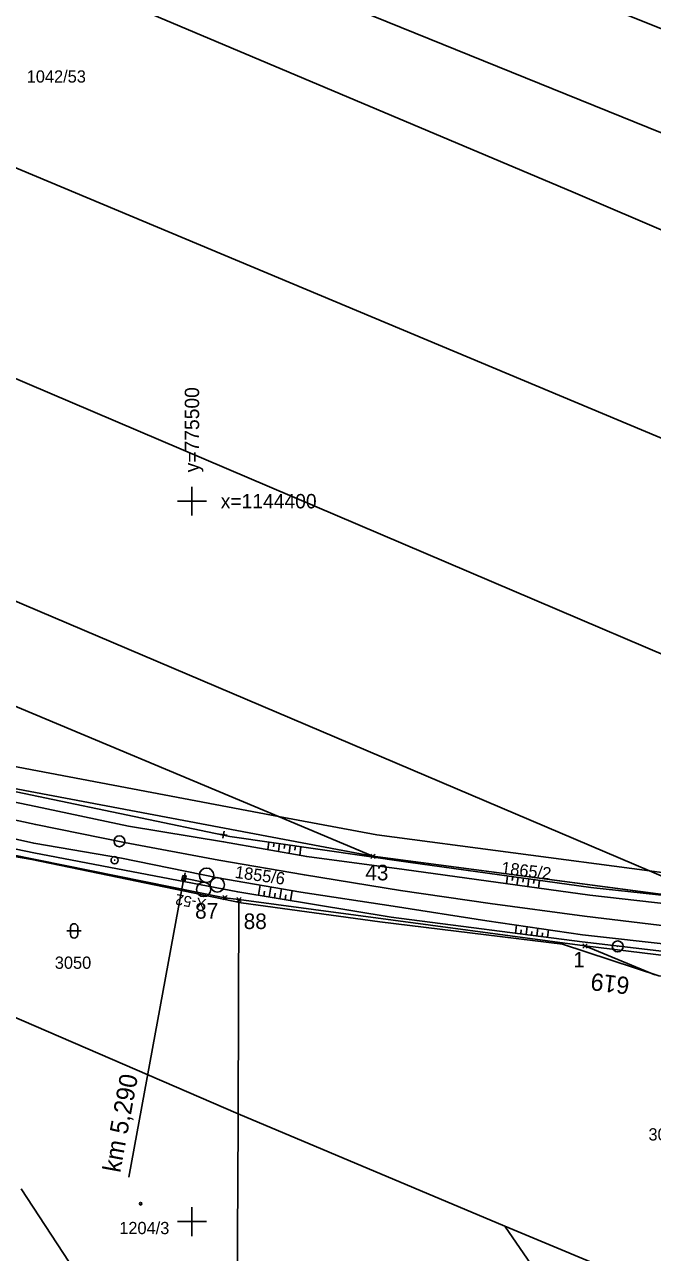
# Model space of a CAD drawing. Extents: x -779302 to -774398, y -1144902 to -1142831.
# Drawn here: x -775523.2 to -775436.1, y -1144504.3 to -1144333.8 of the extents above; entities that cross this region are included whole.
import ezdxf

# ---------------------------------------------------------------- set-up
doc = ezdxf.new("R2010")
doc.units = 0
for name, color, linetype in [('hektosit - Vrstva 5', 7, 'Continuous'), ('Hranice parcel', 7, 'Continuous'), ('legenda I_5_2 - Vrstva 53', 7, 'Continuous'), ('Parcelní čísla', 7, 'Continuous'), ('SŽDC', 7, 'Continuous'), ('zjednodus_g_situ-seda - Vrstva 1', 7, 'Continuous'), ('zjednodus_g_situ-seda - Vrstva 12', 7, 'Continuous'), ('zjednodus_g_situ-seda - Vrstva 17', 7, 'Continuous'), ('zjednodus_g_situ-seda - Vrstva 48', 7, 'Continuous'), ('zjednodus_g_situ-seda - Vrstva 49', 7, 'Continuous'), ('zjednodus_g_situ-seda - Vrstva 63', 7, 'Continuous'), ('zjednodus_g_situ-seda - Vrstva 7', 7, 'Continuous'), ('zjednodus_g_situ-seda - Vrstva 8', 7, 'Continuous'), ('Značky budov', 7, 'Continuous'), ('Značky kultur', 7, 'Continuous')]:
    doc.layers.add(name, color=color, linetype=linetype)

msp = doc.modelspace()

# ---------------------------------------------------------------- linework, layer by layer
at = {"layer": 'hektosit - Vrstva 5'}
for p, q in [((-775500, -1144398), (-775500, -1144402)), ((-775502, -1144400), (-775498, -1144400)), ((-775500, -1144498), (-775500, -1144502)), ((-775502, -1144500), (-775498, -1144500))]:
    msp.add_line(p, q, dxfattribs=at)
at = {"layer": 'Hranice parcel'}
for p, q in [((-775535.75, -1144423.8), (-775487.96, -1144443.76)), ((-775474.88, -1144449.28), (-775487.96, -1144443.76)), ((-775426.17, -1144455.72), (-775474.88, -1144449.28)), ((-775426.17, -1144455.72), (-775436.47, -1144451.33)), ((-775493.58, -1144485.06), (-775493.48, -1144455.3)), ((-775493.48, -1144455.3), (-775445.43, -1144461.73)), ((-775445.43, -1144461.73), (-775435.74, -1144465.74)), ((-775493.58, -1144485.06), (-775539.58, -1144465.16)), ((-775456.54, -1144500.61), (-775493.58, -1144485.06)), ((-775523.71, -1144495.46), (-775507.21, -1144520.6)), ((-775393.05, -1144527.1), (-775456.54, -1144500.61)), ((-775456.54, -1144500.61), (-775385.01, -1144604.68))]:
    msp.add_line(p, q, dxfattribs=at)
for points in [[(-775607.93, -1144251.93), (-775592.73, -1144265.24), (-775577.44, -1144273.94), (-775563.67, -1144281.5), (-775543.76, -1144290.79), (-775411.19, -1144343.87), (-775388.13, -1144354.18)], [(-775632.59, -1144258.06), (-775621.58, -1144265.67), (-775577.27, -1144289.87), (-775522.49, -1144313.33), (-775419.42, -1144355.11), (-775391.09, -1144367.64), (-775389.67, -1144368.26)], [(-775657.22, -1144264.36), (-775641.76, -1144273.65), (-775618.95, -1144284.54), (-775447.05, -1144357.1), (-775391.08, -1144381.09)], [(-775394.06, -1144408.34), (-775619.55, -1144313.89), (-775660.82, -1144292.56), (-775671.23, -1144286.27), (-775688.22, -1144274.1)], [(-775397.11, -1144437.29), (-775575.13, -1144361.42), (-775643.03, -1144333.5), (-775681.69, -1144314.82), (-775705.2, -1144302.37), (-775726.91, -1144287.21)], [(-775773.94, -1144303.16), (-775745.45, -1144320.86), (-775720.13, -1144333.58), (-775665.78, -1144356.01), (-775632.16, -1144368.38), (-775595.92, -1144383.54), (-775436.47, -1144451.33)], [(-775474.88, -1144449.28), (-775529.11, -1144439.07), (-775574.03, -1144428.55), (-775626.91, -1144413.11), (-775690.5, -1144389.48), (-775838.53, -1144328.62), (-775848.16, -1144325.04)], [(-775539.06, -1144434.24), (-775528.56, -1144436.11), (-775487.96, -1144443.76)], [(-775487.96, -1144443.76), (-775474.32, -1144446.33), (-775436.47, -1144451.33)], [(-775532.74, -1144447.53), (-775495.43, -1144455.04), (-775493.48, -1144455.3)], [(-775436.47, -1144451.33), (-775417.75, -1144453.81), (-775384.8, -1144455.7)], [(-775389.68, -1144468.46), (-775425.39, -1144464.15), (-775445.43, -1144461.73)], [(-775489.41, -1144542.39), (-775493.92, -1144534.76), (-775493.7, -1144510.05), (-775493.58, -1144486.33), (-775493.58, -1144485.06)]]:
    msp.add_lwpolyline(points, dxfattribs=at)
at = {"layer": 'legenda I_5_2 - Vrstva 53'}
for points in [[(-776052.08, -1144238.11), (-776022.68, -1144250.27), (-776023.78, -1144252.86), (-775962.18, -1144277.9), (-775959.79, -1144278.81), (-775958.42, -1144279.33), (-775955.63, -1144280.49), (-775876.16, -1144313.52), (-775863.23, -1144318.85), (-775854.19, -1144322.57), (-775848.16, -1144325.04), (-775838.53, -1144328.62), (-775690.5, -1144389.48), (-775626.91, -1144413.11), (-775574.03, -1144428.55), (-775529.11, -1144439.07), (-775474.88, -1144449.28), (-775426.17, -1144455.72)], [(-775425.39, -1144464.15), (-775445.43, -1144461.73), (-775493.48, -1144455.3), (-775495.43, -1144455.04), (-775532.74, -1144447.53), (-775560.62, -1144440.02), (-775576.16, -1144435.84), (-775611.43, -1144425.73), (-775655.04, -1144411.89), (-775699.86, -1144394.42)]]:
    msp.add_lwpolyline(points, dxfattribs=at)
at = {"layer": 'SŽDC'}
for p, q in [((-775474.68, -1144449.48), (-775475.18, -1144448.98)), ((-775474.68, -1144449.08), (-775475.18, -1144449.58)), ((-775475.08, -1144449.48), (-775474.58, -1144448.98)), ((-775475.08, -1144449.08), (-775474.58, -1144449.58)), ((-775474.88, -1144449.28), (-775474.88, -1144449.28)), ((-775495.23, -1144455.24), (-775495.73, -1144454.74)), ((-775495.23, -1144454.84), (-775495.73, -1144455.34)), ((-775495.63, -1144455.24), (-775495.13, -1144454.74)), ((-775495.63, -1144454.84), (-775495.13, -1144455.34)), ((-775495.43, -1144455.04), (-775495.43, -1144455.04)), ((-775493.28, -1144455.5), (-775493.78, -1144455)), ((-775493.28, -1144455.1), (-775493.78, -1144455.6)), ((-775493.68, -1144455.5), (-775493.18, -1144455)), ((-775493.68, -1144455.1), (-775493.18, -1144455.6)), ((-775493.48, -1144455.3), (-775493.48, -1144455.3)), ((-775445.23, -1144461.93), (-775445.73, -1144461.43)), ((-775445.23, -1144461.53), (-775445.73, -1144462.03)), ((-775445.63, -1144461.93), (-775445.13, -1144461.43)), ((-775445.63, -1144461.53), (-775445.13, -1144462.03)), ((-775445.43, -1144461.73), (-775445.43, -1144461.73))]:
    msp.add_line(p, q, dxfattribs=at)
for points in [[(-776052.08, -1144238.11), (-776022.68, -1144250.27), (-776023.78, -1144252.86), (-775962.18, -1144277.9), (-775959.79, -1144278.81), (-775958.42, -1144279.33), (-775955.63, -1144280.49), (-775876.16, -1144313.52), (-775863.23, -1144318.85), (-775854.19, -1144322.57), (-775848.16, -1144325.04), (-775838.53, -1144328.62), (-775690.5, -1144389.48), (-775626.91, -1144413.11), (-775574.03, -1144428.55), (-775529.11, -1144439.07), (-775474.88, -1144449.28), (-775426.17, -1144455.72)], [(-775425.39, -1144464.15), (-775445.43, -1144461.73), (-775493.48, -1144455.3), (-775495.43, -1144455.04), (-775532.74, -1144447.53), (-775560.62, -1144440.02), (-775576.16, -1144435.84), (-775611.43, -1144425.73), (-775655.04, -1144411.89), (-775699.86, -1144394.42)]]:
    msp.add_lwpolyline(points, dxfattribs=at)
at = {"layer": 'zjednodus_g_situ-seda - Vrstva 1'}
msp.add_lwpolyline([(-775432.46, -1144459.19), (-775445.5, -1144457.62), (-775458.59, -1144455.86), (-775471.03, -1144454.03), (-775484.38, -1144451.88), (-775496.27, -1144449.81), (-775509.37, -1144447.36), (-775521.69, -1144444.88), (-775534.17, -1144442.2), (-775545.74, -1144439.57), (-775561.27, -1144435.81), (-775573.85, -1144432.57), (-775585.69, -1144429.37), (-775598.35, -1144425.76), (-775610.54, -1144422.11), (-775625.73, -1144417.32), (-775638.38, -1144413.12), (-775651.31, -1144408.64), (-775662.57, -1144404.57), (-775676.26, -1144399.42), (-775688.29, -1144394.7), (-775696.5, -1144391.38), (-775704.08, -1144388.28), (-775727.95, -1144378.48)], dxfattribs=at)
at = {"layer": 'zjednodus_g_situ-seda - Vrstva 12'}
for p, q in [((-775501.4, -1144452.55), (-775501.39, -1144452.55)), ((-775501.25, -1144451.96), (-775501.25, -1144451.96)), ((-775500.97, -1144452.68), (-775500.96, -1144452.69)), ((-775500.83, -1144452.02), (-775500.82, -1144452.02))]:
    msp.add_line(p, q, dxfattribs=at)
for points in [[(-775500.97, -1144452.68), (-775501.4, -1144452.55), (-775501.25, -1144451.96), (-775500.83, -1144452.02), (-775500.97, -1144452.68)], [(-775501.39, -1144452.55), (-775500.96, -1144452.69), (-775500.82, -1144452.02), (-775501.25, -1144451.96), (-775501.39, -1144452.55)]]:
    msp.add_lwpolyline(points, dxfattribs=at)
at = {"layer": 'zjednodus_g_situ-seda - Vrstva 17'}
msp.add_lwpolyline([(-775529.28, -1144448.55), (-775522.23, -1144449.72), (-775493.17, -1144455.73), (-775473.92, -1144458.39), (-775448.56, -1144461.49), (-775435.18, -1144465.88), (-775406.71, -1144469.31), (-775380.06, -1144472.72)], dxfattribs=at)
at = {"layer": 'zjednodus_g_situ-seda - Vrstva 48'}
for p, q in [((-775489.32, -1144447.32), (-775489.48, -1144448.37)), ((-775488.58, -1144447.42), (-775488.66, -1144447.96)), ((-775487.84, -1144447.53), (-775488, -1144448.63)), ((-775487.1, -1144447.64), (-775487.18, -1144448.2)), ((-775486.35, -1144447.75), (-775486.52, -1144448.9)), ((-775485.61, -1144447.86), (-775485.7, -1144448.44)), ((-775484.87, -1144447.97), (-775485.04, -1144449.16)), ((-775456.21, -1144452.03), (-775456.35, -1144453.1)), ((-775455.46, -1144452.14), (-775455.54, -1144452.67)), ((-775454.72, -1144452.24), (-775454.87, -1144453.3)), ((-775453.98, -1144452.34), (-775454.05, -1144452.87)), ((-775453.23, -1144452.44), (-775453.38, -1144453.5)), ((-775452.49, -1144452.54), (-775452.56, -1144453.08)), ((-775451.75, -1144452.65), (-775451.9, -1144453.71)), ((-775490.77, -1144454.71), (-775490.54, -1144453.31)), ((-775490.03, -1144454.83), (-775489.91, -1144454.14)), ((-775489.29, -1144454.95), (-775489.06, -1144453.57)), ((-775488.55, -1144455.08), (-775488.43, -1144454.39)), ((-775487.81, -1144455.2), (-775487.58, -1144453.82)), ((-775487.07, -1144455.32), (-775486.95, -1144454.63)), ((-775486.33, -1144455.44), (-775486.1, -1144454.08)), ((-775455.1, -1144459.96), (-775454.95, -1144458.84)), ((-775454.35, -1144460.06), (-775454.28, -1144459.51)), ((-775453.61, -1144460.16), (-775453.47, -1144459.06)), ((-775452.87, -1144460.25), (-775452.8, -1144459.71)), ((-775452.12, -1144460.35), (-775451.98, -1144459.28)), ((-775451.38, -1144460.45), (-775451.31, -1144459.92)), ((-775450.63, -1144460.54), (-775450.5, -1144459.5))]:
    msp.add_line(p, q, dxfattribs=at)
at = {"layer": 'zjednodus_g_situ-seda - Vrstva 49'}
for points in [[(-775318.42, -1144461.57), (-775323.45, -1144462.27), (-775349.98, -1144461.82), (-775367.73, -1144461.27), (-775380.03, -1144460.58), (-775393.96, -1144459.59), (-775406.28, -1144458.53), (-775419.87, -1144457.52), (-775444.78, -1144454.69), (-775470.55, -1144451.14), (-775484.05, -1144449.34), (-775495.6, -1144447.28), (-775508.81, -1144445.09), (-775521.66, -1144442.4), (-775533.53, -1144439.91), (-775545.11, -1144437.29), (-775560.56, -1144433.46), (-775571.96, -1144430.35)], [(-775154.54, -1144453.28), (-775157.07, -1144452.49), (-775186.45, -1144454.65), (-775211.52, -1144456.52), (-775233.72, -1144457.95), (-775237.78, -1144458.55), (-775254.76, -1144459.94), (-775280.65, -1144460.69), (-775309.64, -1144461.82), (-775318.42, -1144461.57), (-775322.08, -1144460.68), (-775349.82, -1144460.8), (-775367.7, -1144460.09), (-775380.25, -1144459.29), (-775394.11, -1144458.5), (-775406.17, -1144457.44), (-775418.99, -1144456.41), (-775444.62, -1144453.63), (-775470, -1144450.13), (-775494.73, -1144446.53), (-775521.32, -1144441), (-775544.98, -1144436.05), (-775571.96, -1144430.35)], [(-775432.89, -1144461.62), (-775445.78, -1144460.2), (-775459.04, -1144458.24), (-775472.07, -1144456.21), (-775484.88, -1144454.29), (-775496.42, -1144452.29), (-775509.76, -1144449.56), (-775521.97, -1144447.48), (-775534.78, -1144444.58), (-775546.29, -1144442.15), (-775562.02, -1144438.07), (-775574.22, -1144435)], [(-775136.47, -1144457.15), (-775137.33, -1144459.16), (-775153.73, -1144459.62), (-775186.34, -1144461.91), (-775210.44, -1144464), (-775236.37, -1144465.85), (-775254.41, -1144467.34), (-775280.14, -1144468.53), (-775309.65, -1144469.53), (-775323.06, -1144469.21), (-775350.17, -1144468.93), (-775367.56, -1144468.16), (-775381.28, -1144467.27), (-775394.06, -1144466.38), (-775407.39, -1144465.2), (-775420.28, -1144464.28), (-775434.37, -1144462.51), (-775445.82, -1144461.16), (-775472.35, -1144457.73), (-775493.63, -1144454.24), (-775521.94, -1144448.83), (-775534.74, -1144446.19), (-775546.66, -1144443.43), (-775573.95, -1144436.42)]]:
    msp.add_lwpolyline(points, dxfattribs=at)
at = {"layer": 'zjednodus_g_situ-seda - Vrstva 63'}
msp.add_line((-775440.83, -1144461.8), (-775440.93, -1144461.79), dxfattribs=at)
msp.add_circle((-775440.88, -1144461.8), 0.756, dxfattribs=at)
at = {"layer": 'zjednodus_g_situ-seda - Vrstva 7'}
for p, q in [((-775495.13, -1144446.37), (-775496.12, -1144446.2)), ((-775495.71, -1144446.78), (-775495.54, -1144445.79)), ((-775510.68, -1144449.85), (-775510.78, -1144449.83))]:
    msp.add_line(p, q, dxfattribs=at)
for centre, radius in [((-775510.07, -1144447.21), 0.75), ((-775510.73, -1144449.84), 0.5)]:
    msp.add_circle(centre, radius, dxfattribs=at)
at = {"layer": 'zjednodus_g_situ-seda - Vrstva 8'}
for p, q in [((-775500.96, -1144451.57), (-775501.26, -1144453.04)), ((-775501.11, -1144452.31), (-775508.75, -1144493.81)), ((-775501.11, -1144452.31), (-775498.17, -1144452.91))]:
    msp.add_line(p, q, dxfattribs=at)
for centre in [(-775497.97, -1144451.93), (-775498.37, -1144453.89), (-775496.48, -1144453.25)]:
    msp.add_circle(centre, 1, dxfattribs=at)
at = {"layer": 'Značky budov'}
msp.add_circle((-775507.12, -1144497.52), 0.175, dxfattribs=at)
at = {"layer": 'Značky kultur'}
for p, q in [((-775517.36, -1144459.65), (-775515.36, -1144459.65)), ((-775516.86, -1144459.15), (-775516.86, -1144460.15)), ((-775515.86, -1144460.15), (-775515.86, -1144459.15))]:
    msp.add_line(p, q, dxfattribs=at)
for centre, start, end in [((-775516.36, -1144459.15), 0, 180), ((-775516.36, -1144460.15), 180, 359.9879)]:
    msp.add_arc(centre, 0.5, start, end, dxfattribs=at)

# ---------------------------------------------------------------- texts
at = {"layer": 'hektosit - Vrstva 5'}
msp.add_text('y=775500', height=2, rotation=90, dxfattribs=at).set_placement((-775499, -1144396))
msp.add_text('x=1144400', height=2, dxfattribs=at).set_placement((-775496, -1144401))
at = {"layer": 'Parcelní čísla'}
for s, p in [('1042/53', (-775522.94, -1144341.9)), ('3050', (-775519.04, -1144464.91)), ('3093', (-775436.62, -1144488.74)), ('1204/3', (-775510.09, -1144501.74))]:
    msp.add_text(s, height=1.7, dxfattribs=at).set_placement(p)
for s, rotation, p in [('1855/6', 352, (-775494.1, -1144452.28)), ('1865/2', 353, (-775457.13, -1144451.71))]:
    msp.add_text(s, height=1.7, rotation=rotation, dxfattribs=at).set_placement(p)
at = {"layer": 'SŽDC'}
for s, p in [('43', (-775475.93, -1144452.63)), ('87', (-775499.56, -1144457.95)), ('88', (-775492.82, -1144459.39)), ('1', (-775447.06, -1144464.72))]:
    msp.add_text(s, height=2.16, dxfattribs=at).set_placement(p)
at = {"layer": 'zjednodus_g_situ-seda - Vrstva 63'}
msp.add_text('619', height=2.4, rotation=173.1238, dxfattribs=at).set_placement((-775439.14, -1144466.11))
at = {"layer": 'zjednodus_g_situ-seda - Vrstva 8'}
for s, height, rotation, p in [('X-52', 1.5, 170.0227, (-775497.96, -1144455.25)), ('km 5,290', 2.5, 79.574, (-775509.96, -1144493.3))]:
    msp.add_text(s, height=height, rotation=rotation, dxfattribs=at).set_placement(p)

doc.saveas('drawing.dxf')
